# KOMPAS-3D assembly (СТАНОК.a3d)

Referenced files in D:\СТАНОК\Детали\: Правая продольная балка основания.m3d, Левая продольная балка основания.m3d, Средняя поперечная балка основания.m3d, Задняя поперечная балка основания.m3d, Передняя поперечная балка основания.m3d, Уголок 30х30.m3d, Правый рельс X.m3d, Левый рельс X.m3d
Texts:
  Правая продольная балка основания
  Левая продольная балка основания
  Средняя поперечная балка основания
  Задняя поперечная балка основания
  Передняя поперечная балка основания
  Уголок в основании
